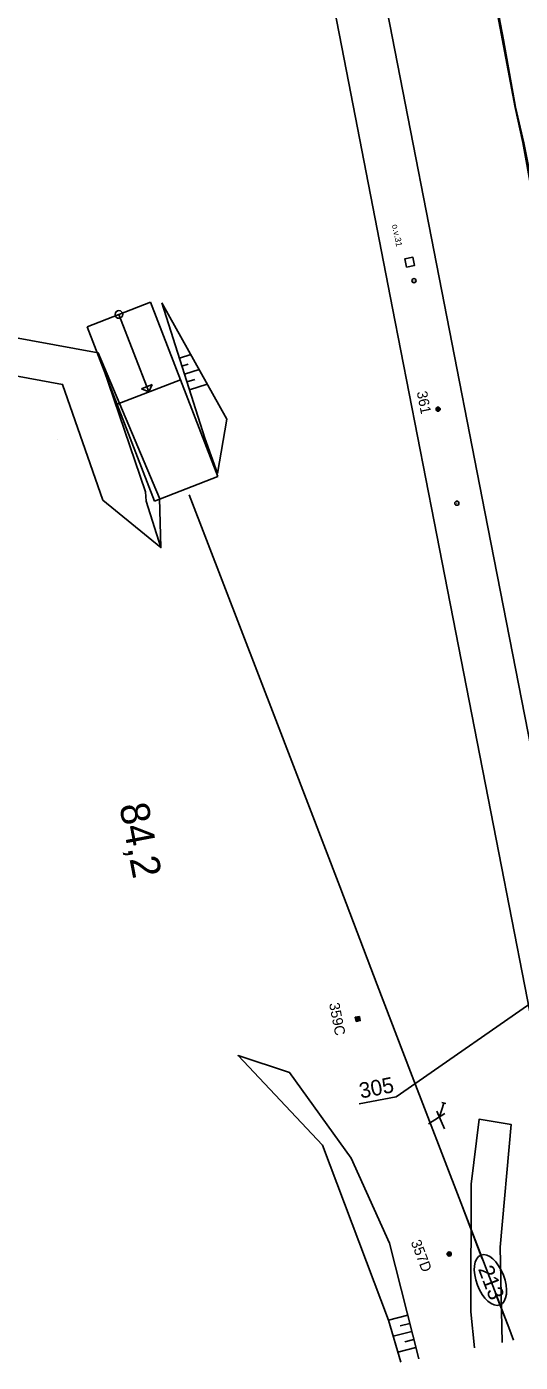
# Model space of a CAD drawing. Extents: x -545967 to -545044, y -1122650 to -1118491.
# Drawn here: x -545804.3 to -545744.9, y -1119256.8 to -1119096.1 of the extents above; entities that cross this region are included whole.
import ezdxf

# ---------------------------------------------------------------- set-up
doc = ezdxf.new("R2010")
doc.units = 0
for name, color, linetype in [('so180602', 7, 'Continuous'), ('Vrstva 1', 7, 'Continuous'), ('Vrstva 11', 7, 'Continuous'), ('Vrstva 19 - Staniceni', 7, 'Continuous'), ('Vrstva 2', 7, 'Continuous'), ('Vrstva 25', 7, 'Continuous'), ('Vrstva 26 - silnoproud', 7, 'Continuous'), ('Vrstva 28', 7, 'Continuous'), ('Vrstva 28 - zabzar', 7, 'Continuous'), ('Vrstva 31', 7, 'Continuous'), ('Vrstva 32', 7, 'Continuous'), ('Vrstva 4', 7, 'Continuous'), ('Vrstva 62', 7, 'Continuous'), ('Vrstva 63', 7, 'Continuous')]:
    doc.layers.add(name, color=color, linetype=linetype)

msp = doc.modelspace()

# ---------------------------------------------------------------- linework, layer by layer
at = {"layer": 'Vrstva 1'}
for points in [[(-545771.03, -1119042.2), (-545765.52, -1119070.46), (-545759.66, -1119100.54), (-545754.32, -1119127.88), (-545749.14, -1119154.44), (-545741.38, -1119194.23), (-545736.64, -1119218.55), (-545732.26, -1119241.01)], [(-545771.69, -1119071.3), (-545765.82, -1119101.41), (-545760.26, -1119129.94), (-545755.25, -1119155.63), (-545747.47, -1119195.48), (-545742.77, -1119219.56), (-545738.37, -1119242.2)], [(-545784.74, -1119152.41), (-545774.31, -1119179.51), (-545766.62, -1119199.55), (-545762.11, -1119211.37), (-545758.11, -1119221.85), (-545752.06, -1119237.57), (-545749.46, -1119244.36)], [(-545747.73, -1119248.86), (-545746.28, -1119252.64), (-545745.7, -1119254.16)]]:
    msp.add_lwpolyline(points, dxfattribs=at)
msp.add_ellipse((-545748.48, -1119246.92), major_axis=(1.15, -3), ratio=0.521067, dxfattribs=at)
at = {"layer": 'Vrstva 11'}
for p, q in [((-545754.64, -1119142.31), (-545755.02, -1119142.05)), ((-545754.53, -1119142.15), (-545754.92, -1119141.9)), ((-545764.16, -1119215.69), (-545764.75, -1119215.3)), ((-545764.42, -1119215.74), (-545764.7, -1119215.56)), ((-545764.21, -1119215.43), (-545764.49, -1119215.24)), ((-545753.27, -1119243.97), (-545753.69, -1119243.78)), ((-545753.2, -1119243.8), (-545753.62, -1119243.61))]:
    msp.add_line(p, q, dxfattribs=at)
msp.add_lwpolyline([(-545764.65, -1119215.78), (-545764.75, -1119215.29), (-545764.26, -1119215.2), (-545764.16, -1119215.69)], close=True, dxfattribs=at)
msp.add_lwpolyline([(-545764.65, -1119215.78), (-545764.75, -1119215.29), (-545764.26, -1119215.2), (-545764.16, -1119215.69), (-545764.65, -1119215.78)], dxfattribs=at)
for centre in [(-545754.78, -1119142.1), (-545753.44, -1119243.78)]:
    msp.add_circle(centre, 0.25, dxfattribs=at)
at = {"layer": 'Vrstva 25'}
msp.add_lwpolyline([(-545758.6, -1119124.99), (-545758.8, -1119124.01), (-545757.81, -1119123.81), (-545757.62, -1119124.79)], close=True, dxfattribs=at)
at = {"layer": 'Vrstva 26 - silnoproud'}
msp.add_lwpolyline([(-545748.72, -1119088.79), (-545745.5, -1119105.78), (-545744.59, -1119110.02), (-545739.38, -1119138.56), (-545737.89, -1119145.12), (-545736.24, -1119151.98), (-545735.25, -1119157.79), (-545734.75, -1119161.66), (-545734.7, -1119163.85), (-545735.24, -1119167.68), (-545737.05, -1119172.51), (-545737.3, -1119173.49), (-545737.95, -1119181.49), (-545735.15, -1119195.91), (-545734.32, -1119200.74), (-545732.62, -1119201.11)], dxfattribs=at)
at = {"layer": 'Vrstva 28'}
for p, q in [((-545757.72, -1119126.64), (-545757.67, -1119126.64)), ((-545752.55, -1119153.42), (-545752.5, -1119153.42))]:
    msp.add_line(p, q, dxfattribs=at)
for centre in [(-545757.69, -1119126.64), (-545752.52, -1119153.42)]:
    msp.add_circle(centre, 0.25, dxfattribs=at)
at = {"layer": 'Vrstva 28 - zabzar'}
msp.add_lwpolyline([(-545724.37, -1119249.99), (-545724.69, -1119248.61), (-545727.23, -1119235.34), (-545728.99, -1119226.34), (-545732.03, -1119209.67), (-545734.16, -1119200.74), (-545735.82, -1119191.07), (-545737.79, -1119181.49), (-545737.14, -1119173.49), (-545736.89, -1119172.51), (-545735.08, -1119167.68), (-545734.54, -1119163.85), (-545734.59, -1119161.66), (-545735.09, -1119157.79), (-545736.08, -1119151.98), (-545737.73, -1119145.12), (-545739.97, -1119133.32), (-545740.77, -1119128.56), (-545744.45, -1119110.05), (-545745.46, -1119105.77), (-545746.9, -1119097.66), (-545750.31, -1119079.79)], dxfattribs=at)
at = {"layer": 'Vrstva 31'}
msp.add_lwpolyline([(-545724.37, -1119249.99), (-545724.69, -1119248.61), (-545727.23, -1119235.34), (-545728.99, -1119226.34), (-545732.03, -1119209.67), (-545734.16, -1119200.74), (-545735.82, -1119191.07), (-545737.79, -1119181.49), (-545737.14, -1119173.49), (-545736.89, -1119172.51), (-545735.08, -1119167.68), (-545734.54, -1119163.85), (-545734.59, -1119161.66), (-545735.09, -1119157.79), (-545736.08, -1119151.98), (-545737.73, -1119145.12), (-545739.97, -1119133.32), (-545740.77, -1119128.56), (-545744.45, -1119110.05), (-545745.46, -1119105.77), (-545746.9, -1119097.66), (-545750.31, -1119079.79)], dxfattribs=at)
at = {"layer": 'Vrstva 32'}
msp.add_lwpolyline([(-545724.37, -1119249.99), (-545724.69, -1119248.61), (-545727.23, -1119235.34), (-545728.99, -1119226.34), (-545732.03, -1119209.67), (-545734.16, -1119200.74), (-545735.66, -1119191.53), (-545735.82, -1119191.07), (-545737.79, -1119181.49), (-545737.14, -1119173.49), (-545736.89, -1119172.51), (-545735.08, -1119167.68), (-545734.54, -1119163.85), (-545734.59, -1119161.66), (-545735.09, -1119157.79), (-545736.08, -1119151.98), (-545737.73, -1119145.12), (-545739.97, -1119133.32), (-545740.77, -1119128.56), (-545744.45, -1119110.05), (-545745.46, -1119105.77), (-545746.9, -1119097.66), (-545750.31, -1119079.79)], dxfattribs=at)
at = {"layer": 'Vrstva 4'}
for p, q in [((-545754.1, -1119225.61), (-545754.62, -1119227.28)), ((-545753.86, -1119225.68), (-545754.34, -1119225.53)), ((-545753.97, -1119226.88), (-545755.93, -1119228.1)), ((-545754.02, -1119228.7), (-545754.93, -1119226.58)), ((-545752.06, -1119237.57), (-545746.28, -1119252.64))]:
    msp.add_line(p, q, dxfattribs=at)
at = {"layer": 'Vrstva 62'}
for p, q in [((-545797.05, -1119132.18), (-545789.4, -1119129.23)), ((-545789.4, -1119129.23), (-545781.29, -1119150.22)), ((-545793.22, -1119130.7), (-545789.62, -1119140.03)), ((-545797.05, -1119132.18), (-545788.94, -1119153.17)), ((-545793.44, -1119141.51), (-545785.79, -1119138.56)), ((-545790.5, -1119139.64), (-545789.23, -1119139.15)), ((-545789.62, -1119140.03), (-545790.5, -1119139.64)), ((-545789.62, -1119140.03), (-545789.23, -1119139.15)), ((-545800.67, -1119145.77), (-545800.67, -1119145.77)), ((-545788.94, -1119153.17), (-545781.29, -1119150.22))]:
    msp.add_line(p, q, dxfattribs=at)
for points in [[(-545826.81, -1119018.24), (-545825.61, -1119037.11), (-545818.4, -1119054.24), (-545811.18, -1119078.05), (-545806.46, -1119086.74), (-545812.22, -1119083.09), (-545825.2, -1119091.84), (-545831.72, -1119104.78), (-545831.78, -1119117.35), (-545828.76, -1119124.33), (-545819.64, -1119130.93), (-545795.72, -1119135.3), (-545790.01, -1119152.05)], [(-545788.17, -1119158.75), (-545795.14, -1119153.04), (-545800.01, -1119139.12), (-545819.83, -1119135.46), (-545830.96, -1119126.16), (-545834.62, -1119117.97), (-545835.22, -1119103.17), (-545829.17, -1119089.96), (-545815.78, -1119081.08), (-545822.6, -1119056.03), (-545830.03, -1119039.13), (-545831.63, -1119019.18)], [(-545781.35, -1119149.86), (-545780.23, -1119143.29), (-545788.05, -1119129.3)], [(-545788.05, -1119129.3), (-545782.89, -1119145.6), (-545781.35, -1119149.86)], [(-545790.01, -1119152.05), (-545789.93, -1119153.17), (-545788.17, -1119158.75), (-545788.35, -1119152.8), (-545795.72, -1119135.3)], [(-545785.94, -1119135.96), (-545784.57, -1119135.53)], [(-545785.64, -1119136.91), (-545784.86, -1119136.67)], [(-545785.34, -1119137.87), (-545783.57, -1119137.31)], [(-545785.04, -1119138.82), (-545784.06, -1119138.51)], [(-545784.73, -1119139.77), (-545782.58, -1119139.09)], [(-545759.26, -1119256.82), (-545760.75, -1119251.74), (-545768.71, -1119230.69), (-545778.87, -1119219.91), (-545772.66, -1119221.93), (-545765.26, -1119232.26), (-545760.62, -1119242.47), (-545757.12, -1119256.4)], [(-545750.39, -1119255.08), (-545750.84, -1119250.74), (-545750.79, -1119235.36), (-545749.84, -1119227.57), (-545745.97, -1119228.21), (-545747.31, -1119242.97), (-545747.06, -1119254.43)], [(-545758.43, -1119251.16), (-545760.75, -1119251.74)], [(-545758.19, -1119252.13), (-545759.33, -1119252.42)], [(-545757.95, -1119253.1), (-545760.19, -1119253.67)], [(-545757.7, -1119254.07), (-545758.8, -1119254.35)], [(-545757.46, -1119255.04), (-545759.62, -1119255.58)]]:
    msp.add_lwpolyline(points, dxfattribs=at)
msp.add_circle((-545793.22, -1119130.7), 0.466, dxfattribs=at)
at = {"layer": 'Vrstva 63'}
for p, q in [((-545731.55, -1119205.2), (-545759.83, -1119224.85)), ((-545759.83, -1119224.85), (-545764.28, -1119225.71))]:
    msp.add_line(p, q, dxfattribs=at)

# ---------------------------------------------------------------- texts
at = {"layer": 'so180602'}
msp.add_text('305', height=1.875, rotation=10.9955, dxfattribs=at).set_placement((-545764.09, -1119225.08))
at = {"layer": 'Vrstva 11'}
for s, rotation, p in [('361', 281.1614, (-545757.36, -1119140.04)), ('359C', 281.1614, (-545767.92, -1119213.66)), ('357D', 290.996, (-545758.09, -1119242.35))]:
    msp.add_text(s, height=1.25, rotation=rotation, dxfattribs=at).set_placement(p)
at = {"layer": 'Vrstva 19 - Staniceni'}
msp.add_text('84,2', height=3.5, rotation=280.8131, dxfattribs=at).set_placement((-545793.18, -1119189.8))
at = {"layer": 'Vrstva 2'}
msp.add_text('213', height=1.875, rotation=290.8781, dxfattribs=at).set_placement((-545749.99, -1119245.58))
at = {"layer": 'Vrstva 25'}
msp.add_text('o.v.31', height=0.75, rotation=281.1614, dxfattribs=at).set_placement((-545760.34, -1119119.92))

doc.saveas('drawing.dxf')
